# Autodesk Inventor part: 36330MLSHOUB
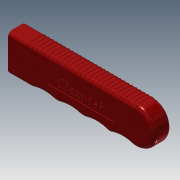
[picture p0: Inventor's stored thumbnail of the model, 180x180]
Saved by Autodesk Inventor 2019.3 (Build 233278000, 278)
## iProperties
Created: 2012-06
Part Number: 36330MLSHOUB
Material: Ogólny
Document SubType Name: Modeling
Designer: CADENGINEERING4
Density: 1 g/cm^3
Appearance: Czerwona
Author: CADENGINEERING4
Revision Number: 2LAST_VERSION
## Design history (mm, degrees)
feature "Baza1"
node "Bryła1"
